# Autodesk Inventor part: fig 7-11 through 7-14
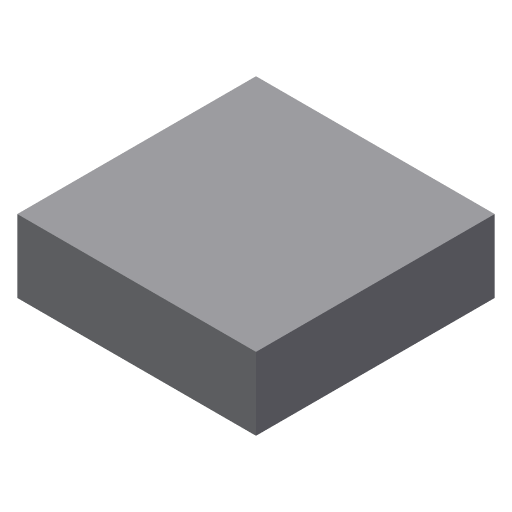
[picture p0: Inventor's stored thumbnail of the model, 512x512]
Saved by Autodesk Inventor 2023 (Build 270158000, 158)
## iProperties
Created: 2009-09
Part Number: fig 7-11 through 7-14
Document SubType Name: Modeling
Designer: Sham
Density: 1 g/cm^3
Material: Generic
Appearance: Default
Author: Sham
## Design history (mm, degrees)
sketch "Sketch1"
  geometry: L1 (-23, 20)-(0, 20); L2 (0, 20)-(0, -3); L3 (0, -3)-(-23, -3); L4 (-23, -3)-(-23, 20)
  constraints: 8 end point, 2 parallel, 1 horizontal, 1 perpendicular
  dimensions: "d2" = 23 distance of L1.start L1.end; "d3" = 23 distance of L3.end L1.start
extrude "Extrusion1" new body sketch "Sketch1" distance "d0" = 7; taper "d1" = 0 deg
body "Solid1"
